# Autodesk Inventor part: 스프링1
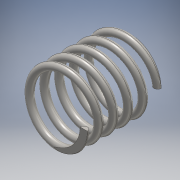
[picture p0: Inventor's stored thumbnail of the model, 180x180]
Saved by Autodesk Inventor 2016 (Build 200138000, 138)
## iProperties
Created: 2019-11
Part Number: 스프링1
Material: 스테인레스 스틸
Document SubType Name: Modeling
Designer: user
Mass: 6.57245 g
Surface Area: 16.7217 cm^2
Volume: 0.821556 cm^3
Density: 8 g/cm^3
Appearance: 반연마
Author: user
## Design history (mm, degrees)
sketch "스케치1"
  geometry: L1 (0, 0)-(8.5, 0); L2 (8.5, 0)-(8.5, 20.5); L3 (8.5, 20.5)-(0, 20.5); L4 (0, 20.5)-(0, 0); C1 r 1 at (8.5, 0)
  constraints: 8 end point, 2 parallel, 1 centre point, 1 coincident, 1 horizontal, 1 perpendicular
  dimensions: "d0" = 20.5 distance between parallel lines of L1 L3 (derived); "d1" = 17 diameter of L2 L4; "d2" = 2 diameter of C1
feature "코일1" sketch "스케치1" pitch "d3" = 10; turns "d5" = 5; dims "d4" = 20.5 (= d0), "d6" = 0, angle "d7" = 90 deg, angle "d8" = 90 deg, "d9" = 0, "d10" = 0
sketch "스케치2"
  geometry: L1 (0, 14.377)-(20.5, 14.377); L2 (20.5, 14.377)-(20.5, -14.377); L3 (20.5, -14.377)-(0, -14.377); L4 (0, -14.377)-(0, 14.377); 2 further points
  constraints: 8 end point, 2 parallel, 1 coincident, 1 horizontal, 1 midpoint, 1 perpendicular
  dimensions: "d11" = 28.75382 distance of L1.end L2.end; "d12" = 20.5 distance between parallel lines of L4 L2 (= d0)
extrude "돌출1" sketch "스케치2" stored distance "d13" = 26.25; taper "d14" = 0 deg
node "솔리드1"
